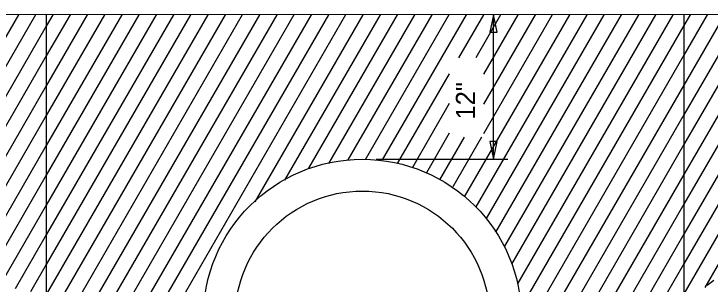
# Model space of a CAD drawing. Extents: x -439.1 to -407.9, y -458.1 to -436.2.
# Drawn here: x -436.13 to -430.66, y -443.27 to -441.15 of the extents above; entities that cross this region are included whole.
import ezdxf

# ---------------------------------------------------------------- set-up
doc = ezdxf.new("R2010")
doc.units = 0
doc.layers.add('Level 4', color=7, linetype='Continuous')
doc.layers.add('Level 45', color=7, linetype='Continuous')

msp = doc.modelspace()

# ---------------------------------------------------------------- linework, layer by layer
at = {"layer": 'Level 4'}
for p, q in [((-438.4434, -441.1503), (-428.1947, -441.1453)), ((-436.098, -441.1514), (-436.9862, -442.6897)), ((-435.9627, -441.1515), (-436.9091, -442.7906)), ((-435.8797, -441.1515), (-435.8797, -443.4378)), ((-435.8275, -441.1515), (-435.8791, -441.241)), ((-435.6921, -441.1515), (-435.8791, -441.4754)), ((-435.5568, -441.1515), (-435.8791, -441.7098)), ((-435.4215, -441.1515), (-435.8791, -441.9442)), ((-435.2862, -441.1515), (-435.8791, -442.1785)), ((-435.1509, -441.1515), (-435.8791, -442.4129)), ((-435.0156, -441.1515), (-435.8791, -442.6473)), ((-434.8802, -441.1515), (-435.8791, -442.8817)), ((-434.7449, -441.1515), (-435.8791, -443.116)), ((-434.6096, -441.1515), (-435.8791, -443.3504)), ((-434.4743, -441.1515), (-435.8248, -443.4907)), ((-434.339, -441.1515), (-435.7352, -443.5698)), ((-434.2037, -441.1515), (-435.64, -443.6394)), ((-434.0684, -441.1515), (-435.545, -443.7092)), ((-433.933, -441.1515), (-435.4466, -443.7731)), ((-433.7977, -441.1515), (-435.3446, -443.8309)), ((-433.6624, -441.1515), (-435.2454, -443.8933)), ((-433.5271, -441.1515), (-435.1504, -443.9632)), ((-433.3918, -441.1515), (-434.2412, -442.6229)), ((-433.2565, -441.1515), (-434.0072, -442.4519)), ((-433.1211, -441.1515), (-433.8181, -442.3588)), ((-432.9858, -441.1515), (-433.6604, -442.3199)), ((-432.8505, -441.1515), (-433.5088, -442.2918)), ((-432.7152, -441.1515), (-433.3735, -442.2918)), ((-432.5799, -441.1515), (-433.2389, -442.2931)), ((-432.4446, -441.1515), (-432.6397, -441.4895)), ((-431.768, -441.1515), (-432.5944, -442.5829)), ((-431.6327, -441.1515), (-432.5048, -442.6622)), ((-432.3092, -441.1515), (-432.5044, -441.4895)), ((-432.1739, -441.1515), (-432.4443, -441.6198)), ((-432.0386, -441.1515), (-432.4443, -441.8541)), ((-431.9033, -441.1515), (-432.4443, -442.0885)), ((-431.4973, -441.1515), (-432.4225, -442.754)), ((-432.3653, -442.2872), (-432.3653, -441.1515)), ((-431.362, -441.1515), (-432.3489, -442.8608)), ((-431.2267, -441.1515), (-432.2777, -442.9719)), ((-431.0914, -441.1515), (-432.224, -443.1133)), ((-430.9561, -441.1515), (-432.1745, -443.2619)), ((-430.8697, -441.1515), (-430.8697, -443.4515)), ((-430.8208, -441.1515), (-430.8692, -441.2354)), ((-430.6854, -441.1515), (-430.8692, -441.4698)), ((-430.5501, -441.1515), (-430.8692, -441.7042)), ((-430.2795, -441.1515), (-430.8692, -442.1729)), ((-430.1442, -441.1515), (-430.8692, -442.4073)), ((-430.0089, -441.1515), (-430.8692, -442.6417)), ((-429.8735, -441.1515), (-430.8692, -442.8761)), ((-429.7382, -441.1515), (-430.8692, -443.1104)), ((-429.6029, -441.1515), (-430.8692, -443.3448)), ((-430.4148, -441.1515), (-430.8692, -441.9386)), ((-429.4676, -441.1515), (-430.7054, -443.2954)), ((-435.8791, -441.241), (-436.8263, -442.8815)), ((-430.8692, -441.2354), (-432.1534, -443.4598)), ((-435.8791, -441.4754), (-436.7105, -442.9154)), ((-430.8692, -441.4698), (-432.1638, -443.7121)), ((-432.7121, -441.615), (-433.1205, -442.3222)), ((-435.8791, -441.7098), (-436.6197, -442.9924)), ((-430.8692, -441.7042), (-432.3893, -444.3371)), ((-432.7121, -441.8493), (-433.002, -442.3514)), ((-430.8692, -441.9386), (-432.254, -444.3371)), ((-435.8791, -441.9442), (-436.5217, -443.057)), ((-432.7121, -442.0837), (-432.8918, -442.3949)), ((-432.5946, -442.1145), (-432.7879, -442.4494)), ((-432.4593, -442.1145), (-432.6841, -442.5039)), ((-435.8791, -442.1785), (-436.4264, -443.1264)), ((-430.8692, -442.1729), (-432.1187, -444.3371)), ((-433.2859, -442.2872), (-432.2528, -442.2872)), ((-435.8791, -442.4129), (-436.332, -443.1973)), ((-430.8692, -442.4073), (-431.935, -444.2533)), ((-435.8791, -442.6473), (-436.2264, -443.2488)), ((-430.8692, -442.6417), (-431.7411, -444.1519)), ((-435.8791, -442.8817), (-436.1236, -443.305)), ((-430.8692, -442.8761), (-431.5117, -443.9889)), ((-435.8791, -443.116), (-436.0021, -443.329)), ((-430.8692, -443.1104), (-431.2737, -443.811))]:
    msp.add_line(p, q, dxfattribs=at)
for points in [[(-432.3366, -441.2898), (-432.3653, -441.1515), (-432.394, -441.2898)], [(-432.394, -442.1489), (-432.3653, -442.2872), (-432.3366, -442.1489)]]:
    msp.add_lwpolyline(points, close=True, dxfattribs=at)
msp.add_lwpolyline([(-430.6324, -443.24), (-430.6853, -443.2809)], dxfattribs=at)
for radius in [1.25, 1.25, 1, 1]:
    msp.add_circle((-433.3952, -443.5372), radius, dxfattribs=at)

# ---------------------------------------------------------------- texts
at = {"layer": 'Level 45'}
msp.add_text('12"', height=0.15, rotation=90, dxfattribs=at).set_placement((-432.5103, -441.9753))

doc.saveas('drawing.dxf')
